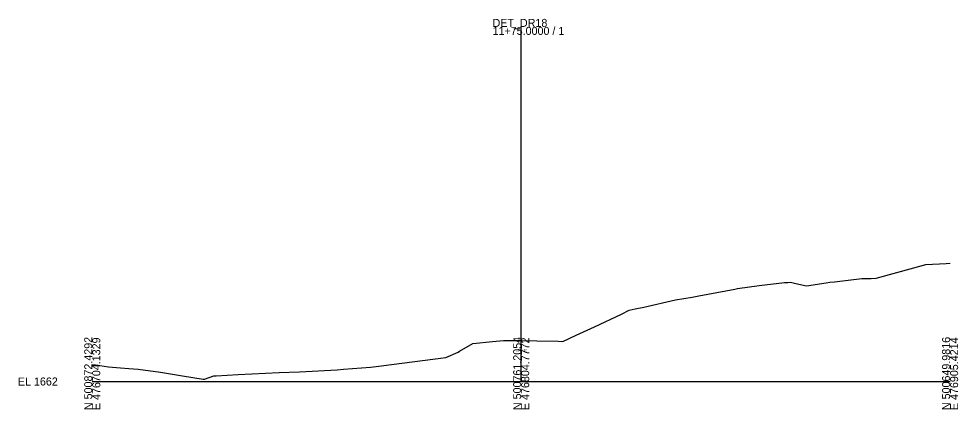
# Model space of a CAD drawing. Extents: x -26 to 303, y -10 to 3627.
# Drawn here: x -25.7 to 302.8, y 3490.3 to 3626.9 of the extents above; entities that cross this region are included whole.
import ezdxf

# ---------------------------------------------------------------- set-up
doc = ezdxf.new("R2010")
doc.units = 0
for name, color, linetype in [('Exist Cross Section Cell', 7, 'Continuous'), ('Exist XS Center Line Elevation Label', 7, 'Continuous'), ('Exist XS Ground Line', 7, 'Continuous')]:
    doc.layers.add(name, color=color, linetype=linetype)

msp = doc.modelspace()

# ---------------------------------------------------------------- linework, layer by layer
at = {"layer": 'Exist Cross Section Cell'}
for p, q in [((150, 3500), (150, 3624.04)), ((0, 3500), (150, 3500)), ((150, 3500), (300, 3500))]:
    msp.add_line(p, q, dxfattribs=at)
at = {"layer": 'Exist XS Ground Line'}
msp.add_lwpolyline([(0, 3505.88), (1.12, 3505.79), (5.69, 3505.11), (9.83, 3504.8), (12.77, 3504.6), (16.02, 3504.32), (23.87, 3503.23), (31.61, 3501.98), (38.75, 3500.86), (39.26, 3500.8), (42.5, 3501.99), (43.39, 3502.04), (51.04, 3502.4), (65.38, 3503.11), (72.51, 3503.41), (85.64, 3504.13), (87.81, 3504.29), (97.31, 3505.02), (100.18, 3505.37), (104.62, 3505.95), (123.69, 3508.38), (127.94, 3510.3), (128.41, 3510.59), (133.04, 3513.27), (139.96, 3514.01), (143.79, 3514.38), (147.07, 3514.36), (150, 3514.32), (155.53, 3514.24), (162.89, 3514.06), (164.57, 3514.05), (169.22, 3516.21), (175.64, 3519.09), (185.04, 3523.54), (187.76, 3524.96), (189.88, 3525.41), (192.88, 3526.02), (203.97, 3528.58), (209.81, 3529.48), (212.16, 3529.91), (224.72, 3532.34), (225.65, 3532.51), (233.24, 3533.57), (242.12, 3534.58), (243.23, 3534.66), (244.15, 3534.75), (246.02, 3534.32), (249.74, 3533.43), (256.64, 3534.5), (258, 3534.74), (259.61, 3534.9), (269.14, 3535.99), (272.43, 3536.04), (274.16, 3536.11), (287.35, 3539.75), (291.51, 3540.89), (298.65, 3541.28), (300, 3541.35)], dxfattribs=at)

# ---------------------------------------------------------------- texts
at = {"layer": 'Exist Cross Section Cell'}
for s, p in [('11+75.0000 / 1', (140, 3621.24)), ('DET_DR18', (140, 3624.04)), ('EL 1662', (-26, 3498.6))]:
    msp.add_text(s, height=2.8, dxfattribs=at).set_placement(p)
for s, p in [('N 500872.4292', (0, 3490)), ('N 500761.2054', (150, 3490)), ('N 500649.9816', (300, 3490)), ('E 476704.1329', (2.8, 3490)), ('E 476804.7772', (152.8, 3490)), ('E 476905.4214', (302.8, 3490))]:
    msp.add_text(s, height=2.8, rotation=90, dxfattribs=at).set_placement(p)
at = {"layer": 'Exist XS Center Line Elevation Label'}
msp.add_text('1676.32', height=0.75, dxfattribs=at).set_placement((148.24, 3510.57))

doc.saveas('drawing.dxf')
